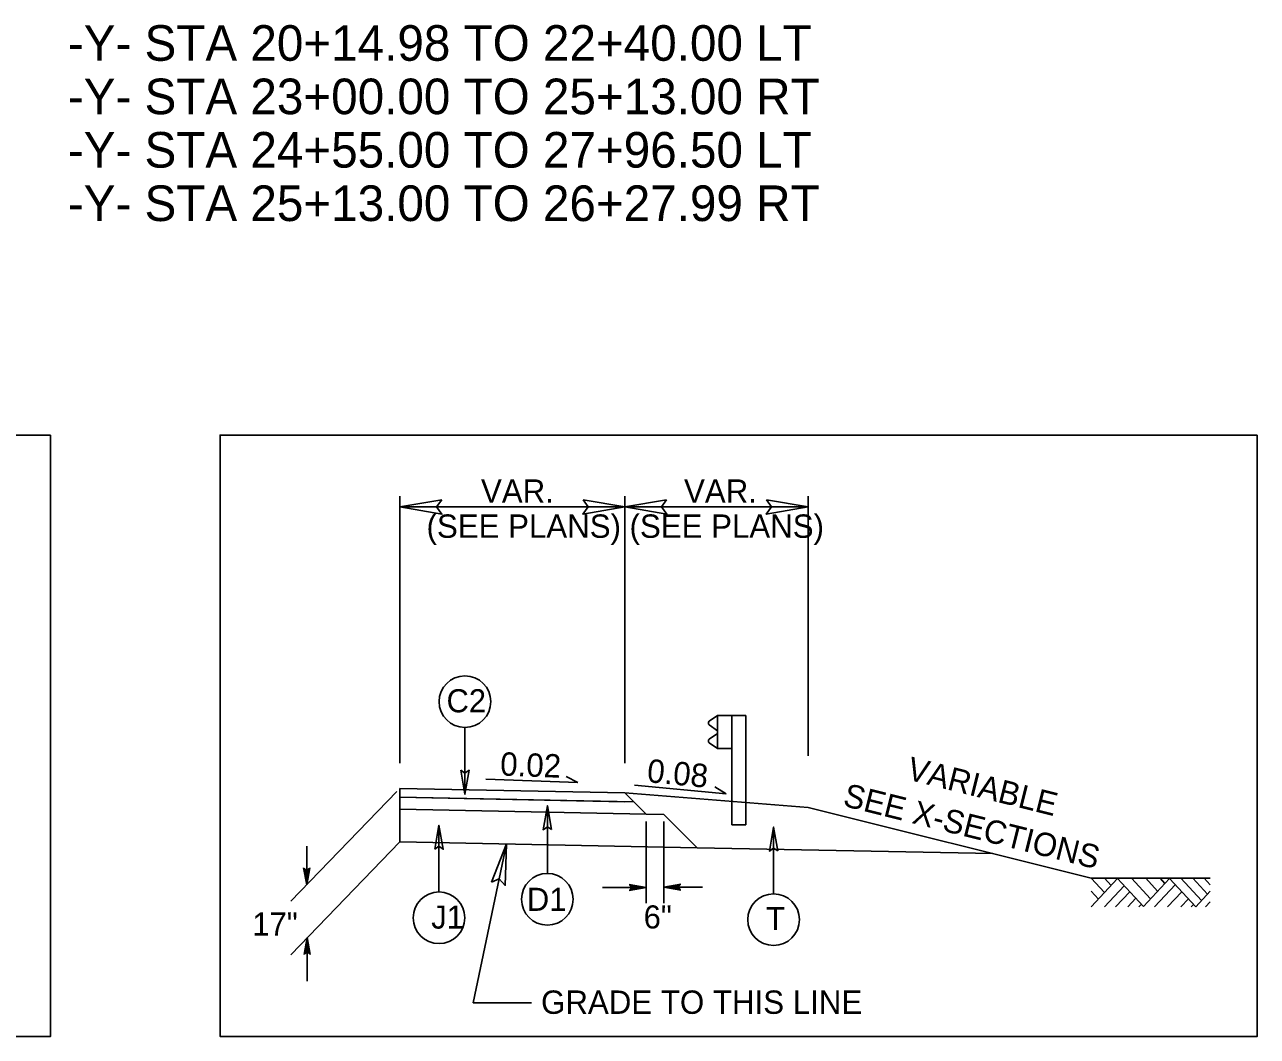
# Model space of a CAD drawing. Extents: x 1901582 to 1902252, y 193723 to 194156.
# Drawn here: x 1902014.52 to 1902049.13, y 193874.77 to 193903.17 of the extents above; entities that cross this region are included whole.
import ezdxf

# ---------------------------------------------------------------- set-up
doc = ezdxf.new("R2010")
doc.units = 0
for name, color, linetype in [('Old_Level_1', 7, 'Continuous'), ('Old_Level_11', 7, 'Continuous'), ('Old_Level_2', 7, 'Continuous'), ('Old_Level_20', 7, 'Continuous'), ('Prop Dimension', 7, 'Continuous'), ('Typical Guardrail CELL', 7, 'Continuous'), ('Typical Terminator CELL', 7, 'Continuous')]:
    doc.layers.add(name, color=color, linetype=linetype)

msp = doc.modelspace()

# ---------------------------------------------------------------- linework, layer by layer
at = {"layer": 'Old_Level_1'}
for p, q in [((1902025.055, 193882.44), (1902025.055, 193889.934)), ((1902031.371, 193882.44), (1902031.371, 193889.934)), ((1902036.519, 193882.639), (1902036.519, 193889.934)), ((1902025.055, 193889.634), (1902031.371, 193889.634)), ((1902031.371, 193889.634), (1902036.519, 193889.634)), ((1902027.462, 193881.992), (1902030.048, 193881.89)), ((1902030.048, 193881.89), (1902029.719, 193882.064)), ((1902024.97, 193881.642), (1902021.987, 193878.559)), ((1902025.055, 193881.729), (1902031.371, 193881.603)), ((1902025.055, 193881.729), (1902025.055, 193880.229)), ((1902031.371, 193881.603), (1902036.519, 193881.191)), ((1902031.371, 193881.603), (1902031.966, 193881.007)), ((1902031.64, 193881.822), (1902034.217, 193881.577)), ((1902034.217, 193881.577), (1902033.897, 193881.768)), ((1902025.055, 193881.479), (1902031.626, 193881.348)), ((1902025.055, 193881.479), (1902031.365, 193881.353)), ((1902025.055, 193881.146), (1902031.966, 193881.007)), ((1902031.966, 193881.007), (1902032.466, 193880.997)), ((1902032.466, 193880.997), (1902033.402, 193880.062)), ((1902036.519, 193881.191), (1902044.465, 193879.204)), ((1902025.055, 193880.229), (1902021.987, 193877.059)), ((1902025.055, 193880.229), (1902033.402, 193880.062)), ((1902022.436, 193880.111), (1902022.436, 193879.023)), ((1902028.047, 193880.169), (1902027.113, 193875.705)), ((1902033.402, 193880.062), (1902041.698, 193879.896)), ((1902022.436, 193879.023), (1902022.351, 193879.5)), ((1902022.436, 193879.023), (1902022.52, 193879.5)), ((1902022.436, 193879.023), (1902022.363, 193879.491)), ((1902022.375, 193879.482), (1902022.436, 193879.023)), ((1902022.436, 193879.023), (1902022.387, 193879.474)), ((1902022.4, 193879.465), (1902022.436, 193879.023)), ((1902022.436, 193879.023), (1902022.412, 193879.456)), ((1902022.424, 193879.447), (1902022.436, 193879.023)), ((1902022.508, 193879.491), (1902022.436, 193879.023)), ((1902022.436, 193879.023), (1902022.495, 193879.482)), ((1902022.483, 193879.474), (1902022.436, 193879.023)), ((1902022.436, 193879.023), (1902022.471, 193879.465)), ((1902022.459, 193879.456), (1902022.436, 193879.023)), ((1902022.436, 193879.023), (1902022.447, 193879.447)), ((1902022.436, 193879.438), (1902022.436, 193879.023)), ((1902031.966, 193878.942), (1902030.741, 193878.942)), ((1902031.966, 193878.942), (1902031.489, 193879.027)), ((1902031.966, 193878.942), (1902031.489, 193878.858)), ((1902031.498, 193879.015), (1902031.966, 193878.942)), ((1902031.966, 193878.942), (1902031.498, 193878.87)), ((1902031.966, 193878.942), (1902031.507, 193879.003)), ((1902031.507, 193878.883), (1902031.966, 193878.942)), ((1902031.516, 193878.991), (1902031.966, 193878.942)), ((1902031.966, 193878.942), (1902031.516, 193878.895)), ((1902031.966, 193878.942), (1902031.524, 193878.978)), ((1902031.524, 193878.907), (1902031.966, 193878.942)), ((1902031.533, 193878.966), (1902031.966, 193878.942)), ((1902031.966, 193878.942), (1902031.533, 193878.919)), ((1902031.966, 193878.942), (1902031.542, 193878.954)), ((1902031.542, 193878.931), (1902031.966, 193878.942)), ((1902032.466, 193878.959), (1902032.943, 193879.043)), ((1902032.466, 193878.959), (1902032.934, 193879.031)), ((1902032.925, 193879.019), (1902032.466, 193878.959)), ((1902032.466, 193878.959), (1902032.917, 193879.007)), ((1902032.908, 193878.995), (1902032.466, 193878.959)), ((1902032.466, 193878.959), (1902032.899, 193878.983)), ((1902032.89, 193878.971), (1902032.466, 193878.959)), ((1902033.554, 193878.959), (1902032.466, 193878.959)), ((1902032.466, 193878.959), (1902032.943, 193878.874)), ((1902032.934, 193878.886), (1902032.466, 193878.959)), ((1902032.466, 193878.959), (1902032.925, 193878.899)), ((1902032.917, 193878.911), (1902032.466, 193878.959)), ((1902032.466, 193878.959), (1902032.908, 193878.923)), ((1902032.899, 193878.935), (1902032.466, 193878.959)), ((1902032.466, 193878.959), (1902032.89, 193878.947)), ((1902032.881, 193878.959), (1902032.466, 193878.959)), ((1902022.452, 193877.54), (1902022.368, 193877.063)), ((1902022.38, 193877.072), (1902022.452, 193877.54)), ((1902022.452, 193877.54), (1902022.392, 193877.081)), ((1902022.404, 193877.09), (1902022.452, 193877.54)), ((1902022.452, 193877.54), (1902022.416, 193877.098)), ((1902022.428, 193877.107), (1902022.452, 193877.54)), ((1902022.452, 193877.54), (1902022.44, 193877.116)), ((1902022.452, 193877.54), (1902022.537, 193877.063)), ((1902022.464, 193877.116), (1902022.452, 193877.54)), ((1902022.452, 193877.54), (1902022.476, 193877.107)), ((1902022.488, 193877.098), (1902022.452, 193877.54)), ((1902022.452, 193877.54), (1902022.5, 193877.09)), ((1902022.512, 193877.081), (1902022.452, 193877.54)), ((1902022.452, 193877.54), (1902022.525, 193877.072)), ((1902022.452, 193877.54), (1902022.452, 193876.315)), ((1902028.748, 193875.705), (1902027.113, 193875.705))]:
    msp.add_line(p, q, dxfattribs=at)
msp.add_lwpolyline([(1902044.465, 193879.204), (1902047.807, 193879.204)], dxfattribs=at)
at = {"layer": 'Old_Level_11'}
for p, q in [((1902026.879, 193883.439), (1902026.879, 193881.565)), ((1902029.194, 193879.34), (1902029.194, 193881.243)), ((1902026.151, 193878.82), (1902026.151, 193880.695)), ((1902035.546, 193878.768), (1902035.546, 193880.642)), ((1902044.465, 193879.204), (1902044.84, 193878.801)), ((1902044.465, 193878.399), (1902045.207, 193879.196)), ((1902044.84, 193879.204), (1902045.027, 193879.003)), ((1902045.207, 193879.196), (1902045.931, 193878.417)), ((1902045.598, 193879.204), (1902046.131, 193878.631)), ((1902045.931, 193878.417), (1902046.662, 193879.203)), ((1902045.996, 193879.204), (1902046.329, 193878.845)), ((1902046.398, 193879.204), (1902046.531, 193879.061)), ((1902046.662, 193879.203), (1902047.403, 193878.407)), ((1902046.984, 193879.204), (1902047.564, 193878.581)), ((1902047.317, 193879.204), (1902047.731, 193878.76)), ((1902047.637, 193879.204), (1902047.807, 193879.021)), ((1902044.465, 193878.842), (1902044.671, 193878.62)), ((1902044.839, 193878.399), (1902045.393, 193878.995)), ((1902045.148, 193878.399), (1902045.549, 193878.828)), ((1902046.241, 193878.399), (1902046.827, 193879.027)), ((1902046.611, 193878.399), (1902047.011, 193878.828)), ((1902047.403, 193878.407), (1902047.807, 193878.842)), ((1902045.495, 193878.399), (1902045.722, 193878.642)), ((1902045.806, 193878.399), (1902045.877, 193878.475)), ((1902046.977, 193878.399), (1902047.194, 193878.632)), ((1902047.272, 193878.399), (1902047.341, 193878.473)), ((1902047.673, 193878.399), (1902047.807, 193878.542))]:
    msp.add_line(p, q, dxfattribs=at)
for points in [[(1902015.245, 193891.651), (1901985.005, 193891.651), (1901985.005, 193874.766), (1902015.245, 193874.766)], [(1902049.129, 193891.651), (1902020.003, 193891.651), (1902020.003, 193874.766), (1902049.129, 193874.766)], [(1902026.764, 193882.237), (1902026.879, 193881.565), (1902026.999, 193882.24), (1902026.879, 193882.155)], [(1902029.309, 193880.571), (1902029.194, 193881.243), (1902029.074, 193880.567), (1902029.194, 193880.653)], [(1902026.036, 193880.023), (1902026.151, 193880.695), (1902026.271, 193880.019), (1902026.151, 193880.105)], [(1902035.662, 193879.971), (1902035.546, 193880.642), (1902035.427, 193879.967), (1902035.546, 193880.053)]]:
    msp.add_lwpolyline(points, close=True, dxfattribs=at)
for centre in [(1902026.879, 193884.165), (1902029.193, 193878.615), (1902026.152, 193878.095), (1902035.546, 193878.043)]:
    msp.add_circle(centre, 0.725, dxfattribs=at)
at = {"layer": 'Prop Dimension'}
for p, q in [((1902031.966, 193878.505), (1902031.966, 193880.798)), ((1902032.466, 193878.505), (1902032.466, 193880.798))]:
    msp.add_line(p, q, dxfattribs=at)
at = {"layer": 'Typical Guardrail CELL'}
for p, q in [((1902033.973, 193883.775), (1902033.741, 193883.612)), ((1902034.371, 193883.775), (1902033.973, 193883.775)), ((1902033.973, 193883.775), (1902033.973, 193882.847)), ((1902034.371, 193883.775), (1902034.371, 193881.363)), ((1902034.371, 193883.775), (1902034.769, 193883.775)), ((1902034.769, 193883.775), (1902034.769, 193881.331)), ((1902033.973, 193883.348), (1902033.741, 193883.51)), ((1902033.973, 193883.311), (1902033.973, 193883.348)), ((1902033.973, 193883.311), (1902033.973, 193883.273)), ((1902033.973, 193883.273), (1902033.741, 193883.111)), ((1902033.973, 193882.847), (1902033.741, 193883.009)), ((1902034.371, 193882.847), (1902033.973, 193882.847)), ((1902034.371, 193881.363), (1902034.371, 193880.709)), ((1902034.769, 193881.331), (1902034.769, 193880.701)), ((1902034.371, 193880.701), (1902034.769, 193880.701))]:
    msp.add_line(p, q, dxfattribs=at)
for centre, start, end in [((1902033.777, 193883.561), 125.003, 235.0112), ((1902033.777, 193883.06), 125.0059, 235.0366)]:
    msp.add_arc(centre, 0.0621, start, end, dxfattribs=at)
at = {"layer": 'Typical Terminator CELL'}
for points in [[(1902026.227, 193889.836), (1902025.055, 193889.634), (1902026.233, 193889.426), (1902026.084, 193889.634)], [(1902030.199, 193889.836), (1902031.371, 193889.634), (1902030.193, 193889.426), (1902030.342, 193889.634)], [(1902032.542, 193889.836), (1902031.371, 193889.634), (1902032.549, 193889.426), (1902032.399, 193889.634)], [(1902035.347, 193889.836), (1902036.519, 193889.634), (1902035.341, 193889.426), (1902035.49, 193889.634)], [(1902027.621, 193879.094), (1902028.047, 193880.169), (1902028.01, 193879.006), (1902027.842, 193879.19)]]:
    msp.add_lwpolyline(points, close=True, dxfattribs=at)

# ---------------------------------------------------------------- texts
at = {"layer": 'Old_Level_1'}
for s, p in [('VAR.', (1902027.33, 193889.749)), ('VAR.', (1902033.031, 193889.749)), ('(SEE PLANS)', (1902025.801, 193888.765)), ('(SEE PLANS)', (1902031.501, 193888.765)), ('GRADE TO THIS LINE', (1902029.017, 193875.398))]:
    msp.add_text(s, height=0.656, dxfattribs=at).set_placement(p)
for s, p in [('VARIABLE', (1902039.256, 193881.988)), ('SEE X-SECTIONS', (1902037.465, 193881.244))]:
    msp.add_text(s, height=0.656, rotation=345.9638, dxfattribs=at).set_placement(p)
at = {"layer": 'Old_Level_11'}
for s, p in [('-Y- STA 20+14.98 TO 22+40.00 LT', (1902015.729, 193902.16)), ('-Y- STA 23+00.00 TO 25+13.00 RT', (1902015.729, 193900.66)), ('-Y- STA 24+55.00 TO 27+96.50 LT', (1902015.729, 193899.16)), ('-Y- STA 25+13.00 TO 26+27.99 RT', (1902015.729, 193897.66))]:
    msp.add_text(s, height=1, dxfattribs=at).set_placement(p)
at = {"layer": 'Old_Level_2'}
for s, rotation, p in [('0.02', 357.7461, (1902027.861, 193882.093)), ('0.08', 354.5855, (1902031.974, 193881.907))]:
    msp.add_text(s, height=0.656, rotation=rotation, dxfattribs=at).set_placement(p)
at = {"layer": 'Old_Level_20'}
for s, height, p in [('C2', 0.6491, (1902026.363, 193883.865)), ('D1', 0.6491, (1902028.619, 193878.29)), ('17"', 0.6491, (1902020.911, 193877.597)), ('J1', 0.6491, (1902025.933, 193877.791)), ('6"', 0.6491, (1902031.898, 193877.795)), ('T', 0.649, (1902035.335, 193877.75))]:
    msp.add_text(s, height=height, dxfattribs=at).set_placement(p)

doc.saveas('drawing.dxf')
